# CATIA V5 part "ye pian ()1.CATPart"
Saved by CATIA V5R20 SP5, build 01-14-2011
Part number: fengshan1
Bounding box of the stored display mesh (mm): x 0 to 148.055, y -45.058 to 54.981, z -2 to 2
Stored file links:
  E:\姜浩然03.08\创意作品\ye pian ()1.CATPart
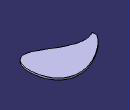
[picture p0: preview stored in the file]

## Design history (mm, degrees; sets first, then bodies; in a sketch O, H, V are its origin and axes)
Body1 (main body)
  Sketch1 on xy-plane, origin (0, 0, 0), H (1, 0, 0), V (0, 1, 0)
    spline S1 through (0, 0) (31.2545, 30.6484) (138.3395, 30.6484) (135.7777, -41.3753) (59.4348, -14.558) (0, -10.4715)
    spline S2 through (0, -10.4715) (0, 0)
    point P1 (0, 0)
    point P2 (0, -10.4715)
    point P3 (0, -10.4715)
    point P4 (0, 0)
    coincidence: P1 O, P2 V, P3 P2, P4 O
  Pad1: profile Sketch1, direction (0, 0, 1), length 1, mirrored extent
  Thickness1: Face end face of Pad1, Thickness 1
